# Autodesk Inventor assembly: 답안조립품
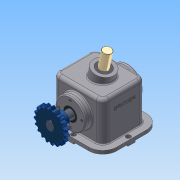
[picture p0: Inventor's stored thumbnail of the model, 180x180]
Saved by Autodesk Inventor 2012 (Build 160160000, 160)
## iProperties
Created: 2014-11
Part Number: 답안조립품
Document SubType Name: Assembly
Designer: User11
Author: User11
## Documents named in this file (13)
- C:\Users\User11\Desktop\441122V1005\답안조립품.iam
- C:\Users\User11\Desktop\441122V1005\1-본체.ipt
- C:\Users\User11\Desktop\441122V1005\뒤커버.ipt
- C:\Users\User11\Desktop\441122V1005\베어링 6205.ipt
- C:\Users\User11\Desktop\441122V1005\편심축.ipt
- C:\Users\User11\Desktop\441122V1005\키 8x8.ipt
- C:\Users\User11\Desktop\441122V1005\슬라이드.ipt
- C:\Users\User11\Desktop\441122V1005\앞커버.ipt
- C:\Users\User11\Desktop\441122V1005\오일실.ipt
- C:\Users\User11\Desktop\441122V1005\5-체인 스프로킷.ipt
- C:\Users\User11\Desktop\441122V1005\M4x0.5.ipt
- C:\Users\User11\Desktop\441122V1005\멈춤나사 M5x0.5.ipt
- C:\Users\User11\Desktop\441122V1005\부시.ipt
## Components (10 placed, 3 different names)
1. 1-본체:1 — 플러쉬:1
2. 5-체인 스프로킷:1 — 각도:2, 플러쉬:3
3. M4x0.5:5
4. M4x0.5:6
5. M4x0.5:7
6. M4x0.5:8
7. M4x0.5:1
8. M4x0.5:2
9. M4x0.5:3
10. M4x0.5:4
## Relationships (3: Flush 2, Angle 1)
- 플러쉬:1 [Flush]: 1-본체:1
- 각도:2 [Angle]: 5-체인 스프로킷:1
- 플러쉬:3 [Flush]: 5-체인 스프로킷:1
